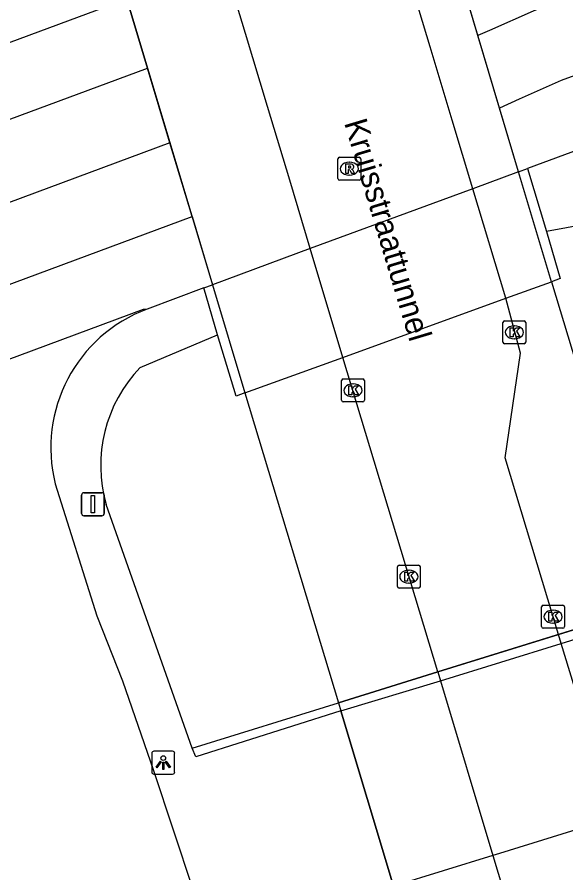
# Model space of a CAD drawing. Extents: x 160806 to 161707, y 383697 to 384148.
# Drawn here: x 161124.06 to 161148.01, y 383843.68 to 383881.02 of the extents above; entities that cross this region are included whole.
import ezdxf

# ---------------------------------------------------------------- set-up
doc = ezdxf.new("R2010")
doc.units = 0
for name, color, linetype in [('IMGEO_Berm_groen', 7, 'Continuous'), ('IMGEO_Fietspad_gesloten', 7, 'Continuous'), ('IMGEO_Groenvoorziening', 7, 'Continuous'), ('IMGEO_Kolk', 7, 'Continuous'), ('IMGEO_Lichtpunt', 7, 'Continuous'), ('IMGEO_Muur', 7, 'Continuous'), ('IMGEO_Openbare_ruimte_label', 7, 'Continuous'), ('IMGEO_OVBaan_gesloten', 7, 'Continuous'), ('IMGEO_Rijbaan_lokaal_gesloten', 7, 'Continuous'), ('IMGEO_Rioolput', 7, 'Continuous'), ('IMGEO_Tunneldeel', 7, 'Continuous'), ('IMGEO_Verkeersbordpaal', 7, 'Continuous'), ('IMGEO_Voetpad_open', 7, 'Continuous')]:
    doc.layers.add(name, color=color, linetype=linetype)

msp = doc.modelspace()

# ---------------------------------------------------------------- linework, layer by layer
at = {"layer": 'IMGEO_Berm_groen'}
msp.add_lwpolyline([(161150.814, 383872.34), (161147.163, 383871.675)], dxfattribs=at)
at = {"layer": 'IMGEO_Fietspad_gesloten'}
for points in [[(161145.381, 383868.752), (161143.943, 383873.537), (161143.043, 383876.531), (161142.082, 383879.729), (161141.127, 383882.908), (161140.189, 383886.03), (161139.898, 383886.998), (161139.762, 383887.449)], [(161138.282, 383866.176), (161136.85, 383870.932), (161135.955, 383873.904), (161134.987, 383877.121), (161134.025, 383880.315), (161133.097, 383883.398), (161132.802, 383884.376), (161132.666, 383884.829)], [(161138.282, 383866.176), (161145.381, 383868.752)], [(161138.282, 383866.176), (161145.381, 383868.752)], [(161147.686, 383854.079), (161147.449, 383854.857), (161145.358, 383861.789), (161146.034, 383866.359), (161145.381, 383868.752)], [(161142.416, 383852.446), (161138.282, 383866.176)], [(161147.686, 383854.079), (161142.416, 383852.446)], [(161153.099, 383836.327), (161150.124, 383846.082), (161147.804, 383853.693), (161147.686, 383854.079)], [(161142.416, 383852.446), (161142.534, 383852.055), (161144.827, 383844.441), (161145.8, 383841.21), (161146.837, 383837.764), (161147.656, 383835.045), (161147.77, 383834.67)]]:
    msp.add_lwpolyline(points, dxfattribs=at)
at = {"layer": 'IMGEO_Groenvoorziening'}
for points in [[(161129.436, 383865.731), (161132.81, 383867.162)], [(161131.695, 383849.124), (161127.952, 383859.751)], [(161140.482, 383843.096), (161138.194, 383850.745)]]:
    msp.add_lwpolyline(points, dxfattribs=at)
msp.add_arc((161133.83, 383861.466), 6.123, 135.8568, 196.2692, dxfattribs=at)
at = {"layer": 'IMGEO_Kolk'}
for p, q in [((161145.26, 383866.843), (161145.26, 383867.695)), ((161145.335, 383867.769), (161146.187, 383867.769)), ((161146.261, 383867.695), (161146.261, 383866.843)), ((161145.748, 383867.549), (161145.773, 383867.549)), ((161145.771, 383866.989), (161145.746, 383866.989)), ((161146.187, 383866.769), (161145.335, 383866.769)), ((161138.218, 383864.308), (161138.218, 383865.16)), ((161138.293, 383865.234), (161139.145, 383865.234)), ((161139.219, 383865.16), (161139.219, 383864.308)), ((161138.706, 383865.014), (161138.731, 383865.014)), ((161138.729, 383864.454), (161138.704, 383864.454)), ((161139.145, 383864.234), (161138.293, 383864.234)), ((161140.656, 383856.18), (161140.656, 383857.032)), ((161140.731, 383857.106), (161141.583, 383857.106)), ((161141.144, 383856.886), (161141.169, 383856.886)), ((161141.657, 383857.032), (161141.657, 383856.18)), ((161141.583, 383856.106), (161140.731, 383856.106)), ((161141.167, 383856.326), (161141.142, 383856.326)), ((161147.023, 383855.357), (161147.875, 383855.357)), ((161146.948, 383854.431), (161146.948, 383855.283)), ((161147.436, 383855.137), (161147.461, 383855.137)), ((161147.949, 383855.283), (161147.949, 383854.431)), ((161147.875, 383854.357), (161147.023, 383854.357)), ((161147.459, 383854.577), (161147.434, 383854.577))]:
    msp.add_line(p, q, dxfattribs=at)
for points in [[(161145.26, 383866.843), (161145.26, 383867.695)], [(161145.335, 383867.769), (161146.187, 383867.769)], [(161146.261, 383867.695), (161146.261, 383866.843)], [(161145.581, 383867.469), (161145.704, 383867.469), (161145.704, 383867.318), (161145.834, 383867.469), (161145.998, 383867.469), (161145.852, 383867.318), (161146.005, 383867.069), (161145.853, 383867.069), (161145.768, 383867.233), (161145.704, 383867.166), (161145.704, 383867.069), (161145.581, 383867.069), (161145.581, 383867.469)], [(161146.187, 383866.769), (161145.335, 383866.769)], [(161138.218, 383864.308), (161138.218, 383865.16)], [(161138.293, 383865.234), (161139.145, 383865.234)], [(161139.219, 383865.16), (161139.219, 383864.308)], [(161138.539, 383864.934), (161138.662, 383864.934), (161138.662, 383864.783), (161138.792, 383864.934), (161138.956, 383864.934), (161138.81, 383864.783), (161138.963, 383864.534), (161138.811, 383864.534), (161138.726, 383864.698), (161138.662, 383864.631), (161138.662, 383864.534), (161138.539, 383864.534), (161138.539, 383864.934)], [(161139.145, 383864.234), (161138.293, 383864.234)], [(161140.656, 383856.18), (161140.656, 383857.032)], [(161140.731, 383857.106), (161141.583, 383857.106)], [(161141.657, 383857.032), (161141.657, 383856.18)], [(161140.977, 383856.806), (161141.1, 383856.806), (161141.1, 383856.655), (161141.23, 383856.806), (161141.394, 383856.806), (161141.248, 383856.655), (161141.401, 383856.406), (161141.249, 383856.406), (161141.164, 383856.57), (161141.1, 383856.503), (161141.1, 383856.406), (161140.977, 383856.406), (161140.977, 383856.806)], [(161141.583, 383856.106), (161140.731, 383856.106)], [(161147.023, 383855.357), (161147.875, 383855.357)], [(161146.948, 383854.431), (161146.948, 383855.283)], [(161147.269, 383855.057), (161147.392, 383855.057), (161147.392, 383854.906), (161147.522, 383855.057), (161147.686, 383855.057), (161147.54, 383854.906), (161147.693, 383854.657), (161147.541, 383854.657), (161147.456, 383854.821), (161147.392, 383854.754), (161147.392, 383854.657), (161147.269, 383854.657), (161147.269, 383855.057)], [(161147.949, 383855.283), (161147.949, 383854.431)], [(161147.875, 383854.357), (161147.023, 383854.357)]]:
    msp.add_lwpolyline(points, dxfattribs=at)
for centre, start, end in [((161145.337, 383867.693), 91.552, 178.448), ((161145.337, 383867.693), 91.552, 178.448), ((161146.185, 383867.693), 1.552, 88.448), ((161146.185, 383867.693), 1.552, 88.448), ((161145.337, 383866.845), 181.552, 268.448), ((161145.337, 383866.845), 181.552, 268.448), ((161146.185, 383866.845), 271.552, 358.448), ((161146.185, 383866.845), 271.552, 358.448), ((161138.295, 383865.158), 91.552, 178.448), ((161138.295, 383865.158), 91.552, 178.448), ((161139.143, 383865.158), 1.552, 88.448), ((161139.143, 383865.158), 1.552, 88.448), ((161138.295, 383864.31), 181.552, 268.448), ((161138.295, 383864.31), 181.552, 268.448), ((161139.143, 383864.31), 271.552, 358.448), ((161139.143, 383864.31), 271.552, 358.448), ((161140.733, 383857.03), 91.552, 178.448), ((161140.733, 383857.03), 91.552, 178.448), ((161141.581, 383857.03), 1.552, 88.448), ((161141.581, 383857.03), 1.552, 88.448), ((161140.733, 383856.182), 181.552, 268.448), ((161140.733, 383856.182), 181.552, 268.448), ((161141.581, 383856.182), 271.552, 358.448), ((161141.581, 383856.182), 271.552, 358.448), ((161147.025, 383855.281), 91.552, 178.448), ((161147.025, 383855.281), 91.552, 178.448), ((161147.873, 383855.281), 1.552, 88.448), ((161147.873, 383855.281), 1.552, 88.448), ((161147.025, 383854.433), 181.552, 268.448), ((161147.025, 383854.433), 181.552, 268.448), ((161147.873, 383854.433), 271.552, 358.448), ((161147.873, 383854.433), 271.552, 358.448)]:
    msp.add_arc(centre, 0.0765, start, end, dxfattribs=at)
for centre, major_axis, ratio, start_param, end_param in [((161145.747, 383867.269), (-0.387, 0.002), 0.722429, 4.712389, 7.853982), ((161145.772, 383867.269), (-0.39, 0.002), 0.717154, 1.570796, 4.712389), ((161138.705, 383864.734), (-0.387, 0.002), 0.722429, 4.712389, 7.853982), ((161138.73, 383864.734), (-0.39, 0.002), 0.717154, 1.570796, 4.712389), ((161141.143, 383856.606), (-0.387, 0.002), 0.722429, 4.712389, 7.853982), ((161141.168, 383856.606), (-0.39, 0.002), 0.717154, 1.570796, 4.712389), ((161147.435, 383854.857), (-0.387, 0.002), 0.722429, 4.712389, 7.853982), ((161147.46, 383854.857), (-0.39, 0.002), 0.717154, 1.570796, 4.712389)]:
    msp.add_ellipse(centre, major_axis=major_axis, ratio=ratio, start_param=start_param, end_param=end_param, dxfattribs=at)
at = {"layer": 'IMGEO_Lichtpunt'}
for p, q in [((161129.94, 383848.891), (161129.94, 383848.084)), ((161129.94, 383848.891), (161129.94, 383848.084)), ((161130.842, 383848.986), (161130.034, 383848.986)), ((161130.842, 383848.986), (161130.034, 383848.986)), ((161130.936, 383848.084), (161130.936, 383848.891)), ((161130.936, 383848.084), (161130.936, 383848.891)), ((161130.034, 383847.99), (161130.842, 383847.99)), ((161130.034, 383847.99), (161130.842, 383847.99))]:
    msp.add_line(p, q, dxfattribs=at)
for points in [[(161130.314, 383848.555), (161130.353, 383848.527), (161130.165, 383848.265), (161130.127, 383848.292), (161130.314, 383848.555)], [(161130.416, 383848.507), (161130.463, 383848.507), (161130.463, 383848.185), (161130.416, 383848.185), (161130.416, 383848.507)], [(161130.526, 383848.527), (161130.564, 383848.554), (161130.751, 383848.292), (161130.712, 383848.264), (161130.526, 383848.527)]]:
    msp.add_lwpolyline(points, dxfattribs=at)
msp.add_circle((161130.439, 383848.689), 0.0994, dxfattribs=at)
for centre, start, end in [((161130.034, 383848.891), 90, 180), ((161130.034, 383848.891), 90, 180), ((161130.842, 383848.891), 0, 90), ((161130.842, 383848.891), 0, 90), ((161130.034, 383848.084), 180, 270), ((161130.034, 383848.084), 180, 270), ((161130.842, 383848.084), 270, 0), ((161130.842, 383848.084), 270, 360)]:
    msp.add_arc(centre, 0.0946, start, end, dxfattribs=at)
at = {"layer": 'IMGEO_Muur'}
for points in [[(161145.945, 383874.273), (161146.332, 383874.416)], [(161146.332, 383874.416), (161147.163, 383871.675)], [(161147.376, 383869.475), (161145.945, 383874.273)], [(161147.163, 383871.675), (161147.756, 383869.613), (161147.376, 383869.475)], [(161132.21, 383869.205), (161132.588, 383869.346)], [(161132.81, 383867.162), (161132.21, 383869.205)], [(161132.588, 383869.346), (161134.004, 383864.624)], [(161134.004, 383864.624), (161133.615, 383864.483), (161132.81, 383867.162)], [(161147.686, 383854.079), (161149.611, 383854.676), (161151.661, 383855.311)], [(161138.194, 383850.745), (161142.534, 383852.055), (161147.804, 383853.693), (161149.727, 383854.291), (161151.776, 383854.928)], [(161142.416, 383852.446), (161147.686, 383854.079)], [(161138.086, 383851.104), (161142.416, 383852.446)], [(161131.695, 383849.124), (161138.086, 383851.104)], [(161138.086, 383851.104), (161138.194, 383850.745)], [(161138.194, 383850.745), (161131.856, 383848.736), (161131.695, 383849.124)]]:
    msp.add_lwpolyline(points, dxfattribs=at)
at = {"layer": 'IMGEO_OVBaan_gesloten'}
msp.add_lwpolyline([(161151.764, 383846.764), (161151.824, 383846.609), (161150.124, 383846.082), (161145.114, 383844.53), (161144.827, 383844.441), (161140.482, 383843.096)], dxfattribs=at)
at = {"layer": 'IMGEO_Rijbaan_lokaal_gesloten'}
for points in [[(161214.088, 383901.528), (161187.391, 383894.279), (161172.114, 383889.9), (161162.606, 383886.956), (161151.326, 383883.114), (161148.429, 383882.073), (161146.576, 383881.284), (161144.681, 383880.444), (161144.172, 383880.216)], [(161215.028, 383898.347), (161189.294, 383891.393), (161174.166, 383886.995), (161163.764, 383883.81), (161154.369, 383880.657), (161147.808, 383878.255), (161145.964, 383877.441), (161145.116, 383877.053)], [(161144.172, 383880.216), (161143.232, 383883.37)], [(161128.848, 383881.822), (161087.876, 383866.621)], [(161129.754, 383878.799), (161128.848, 383881.822)], [(161145.116, 383877.053), (161144.172, 383880.216)], [(161070.422, 383856.806), (161129.754, 383878.799)], [(161130.73, 383875.543), (161129.754, 383878.799)], [(161145.945, 383874.273), (161145.116, 383877.053)], [(161151.735, 383876.413), (161146.332, 383874.416)], [(161130.73, 383875.543), (161100.785, 383864.404), (161068.088, 383852.305), (161054.975, 383847.445), (161009.318, 383830.547), (161001.838, 383827.792), (160966.768, 383814.836)], [(161131.695, 383872.323), (161130.73, 383875.543)], [(161145.945, 383874.273), (161143.943, 383873.537), (161136.85, 383870.932), (161132.588, 383869.346)], [(161059.41, 383845.762), (161062.999, 383847.001), (161070.515, 383849.722), (161085.394, 383855.134), (161131.695, 383872.323)], [(161131.695, 383872.323), (161132.588, 383869.346)], [(161132.21, 383869.205), (161129.731, 383868.28)], [(161129.731, 383868.28), (161129.555, 383868.265), (161106.205, 383859.577)], [(161125.724, 383860.653), (161127.533, 383854.899), (161128.653, 383852.066), (161130.01, 383848.147), (161131.736, 383842.961)]]:
    msp.add_lwpolyline(points, dxfattribs=at)
msp.add_arc((161131.996, 383862.224), 6.466, 110.5051, 194.0627, dxfattribs=at)
at = {"layer": 'IMGEO_Rioolput'}
for p, q in [((161138.058, 383873.981), (161138.058, 383874.833)), ((161138.133, 383874.907), (161138.985, 383874.907)), ((161139.059, 383874.833), (161139.059, 383873.981)), ((161138.546, 383874.687), (161138.571, 383874.687)), ((161138.569, 383874.127), (161138.544, 383874.127)), ((161138.985, 383873.907), (161138.133, 383873.907))]:
    msp.add_line(p, q, dxfattribs=at)
for points in [[(161138.058, 383873.981), (161138.058, 383874.833)], [(161138.133, 383874.907), (161138.985, 383874.907)], [(161139.059, 383874.833), (161139.059, 383873.981)], [(161138.647, 383874.605), (161138.395, 383874.607), (161138.395, 383874.207)], [(161138.573, 383874.526), (161138.519, 383874.526), (161138.519, 383874.445)], [(161138.519, 383874.445), (161138.571, 383874.445)], [(161138.395, 383874.207), (161138.519, 383874.207), (161138.519, 383874.369), (161138.53, 383874.369)], [(161138.577, 383874.34), (161138.648, 383874.207), (161138.788, 383874.207), (161138.723, 383874.333)], [(161138.985, 383873.907), (161138.133, 383873.907)]]:
    msp.add_lwpolyline(points, dxfattribs=at)
for centre, radius, start, end in [((161138.135, 383874.831), 0.0765, 91.552, 178.448), ((161138.135, 383874.831), 0.0765, 91.552, 178.448), ((161138.983, 383874.831), 0.0765, 1.552, 88.448), ((161138.983, 383874.831), 0.0765, 1.552, 88.448), ((161138.555, 383874.634), 0.19, 274.7715, 282.9687), ((161138.579, 383874.43), 0.0964, 77.0061, 93.1865), ((161138.593, 383874.487), 0.0378, 276.6634, 79.6772), ((161138.646, 383874.495), 0.109, 350.3612, 89.416), ((161138.644, 383874.495), 0.112, 277.5842, 350.9817), ((161138.529, 383874.316), 0.0533, 26.0293, 88.6989), ((161138.628, 383874.28), 0.108, 29.5134, 73.7905), ((161138.135, 383873.983), 0.0765, 181.552, 268.448), ((161138.135, 383873.983), 0.0765, 181.552, 268.448), ((161138.983, 383873.983), 0.0765, 271.552, 358.448), ((161138.983, 383873.983), 0.0765, 271.552, 358.448)]:
    msp.add_arc(centre, radius, start, end, dxfattribs=at)
for centre, major_axis, ratio, start_param, end_param in [((161138.545, 383874.407), (-0.387, 0.002), 0.722429, 4.712389, 7.853982), ((161138.57, 383874.407), (-0.39, 0.002), 0.717154, 1.570796, 4.712389)]:
    msp.add_ellipse(centre, major_axis=major_axis, ratio=ratio, start_param=start_param, end_param=end_param, dxfattribs=at)
at = {"layer": 'IMGEO_Tunneldeel'}
for points in [[(161142.214, 383886.781), (161141.926, 383887.748), (161141.791, 383888.198), (161139.762, 383887.449), (161132.666, 383884.829), (161128.417, 383883.26), (161128.299, 383883.216), (161128.402, 383882.878), (161128.519, 383882.921), (161128.553, 383882.806), (161128.848, 383881.822), (161132.588, 383869.346), (161134.004, 383864.624), (161138.282, 383866.176), (161145.381, 383868.752), (161147.376, 383869.475), (161145.945, 383874.273)], [(161154.024, 383847.47), (161153.895, 383847.899), (161153.748, 383848.385), (161153.573, 383848.966), (161151.776, 383854.928), (161151.661, 383855.311), (161149.611, 383854.676), (161142.416, 383852.446), (161138.086, 383851.104), (161138.194, 383850.745), (161140.482, 383843.096), (161142.482, 383836.411), (161143.295, 383833.692), (161143.408, 383833.314), (161147.77, 383834.67), (161154.96, 383836.906), (161157.016, 383837.543), (161156.904, 383837.916), (161156.084, 383840.634)]]:
    msp.add_lwpolyline(points, close=True, dxfattribs=at)
at = {"layer": 'IMGEO_Verkeersbordpaal'}
for p, q in [((161126.973, 383860.266), (161127.763, 383860.266)), ((161127.763, 383860.266), (161126.973, 383860.266)), ((161126.873, 383859.366), (161126.873, 383860.166)), ((161126.873, 383860.166), (161126.873, 383859.366)), ((161127.863, 383860.166), (161127.863, 383859.366)), ((161127.863, 383859.366), (161127.863, 383860.166)), ((161127.763, 383859.266), (161126.973, 383859.266)), ((161126.973, 383859.266), (161127.763, 383859.266))]:
    msp.add_line(p, q, dxfattribs=at)
msp.add_lwpolyline([(161127.293, 383860.141), (161127.443, 383860.141), (161127.443, 383859.391), (161127.293, 383859.391), (161127.293, 383860.141)], dxfattribs=at)
for centre, start, end in [((161126.973, 383860.166), 90, 180), ((161126.973, 383860.166), 90, 180), ((161127.763, 383860.166), 0, 90), ((161127.763, 383860.166), 360, 90), ((161126.973, 383859.366), 180, 270), ((161126.973, 383859.366), 180, 270), ((161127.763, 383859.366), 270, 0), ((161127.763, 383859.366), 270, 0)]:
    msp.add_arc(centre, 0.1, start, end, dxfattribs=at)
at = {"layer": 'IMGEO_Voetpad_open'}
for points in [[(161145.381, 383868.752), (161147.376, 383869.475), (161145.945, 383874.273), (161142.214, 383886.781), (161141.926, 383887.748), (161141.791, 383888.198), (161139.762, 383887.449)], [(161132.666, 383884.829), (161128.417, 383883.26), (161128.299, 383883.216), (161128.402, 383882.878), (161128.519, 383882.921), (161128.553, 383882.806), (161128.848, 383881.822), (161132.588, 383869.346), (161134.004, 383864.624), (161138.282, 383866.176)], [(161145.381, 383868.752), (161147.376, 383869.475)], [(161147.376, 383869.475), (161149.378, 383862.885)], [(161134.004, 383864.624), (161138.282, 383866.176)], [(161134.004, 383864.624), (161138.086, 383851.104)], [(161153.099, 383836.327), (161154.96, 383836.906), (161157.016, 383837.543), (161156.904, 383837.916), (161156.084, 383840.634), (161154.024, 383847.47), (161153.895, 383847.899), (161153.748, 383848.385), (161153.573, 383848.966), (161151.776, 383854.928), (161151.661, 383855.311), (161149.611, 383854.676), (161147.686, 383854.079)], [(161142.416, 383852.446), (161138.086, 383851.104), (161138.194, 383850.745), (161140.482, 383843.096), (161142.482, 383836.411), (161143.295, 383833.692), (161143.408, 383833.314), (161147.77, 383834.67)]]:
    msp.add_lwpolyline(points, dxfattribs=at)

# ---------------------------------------------------------------- texts
at = {"layer": 'IMGEO_Openbare_ruimte_label'}
msp.add_text('Kruisstraattunnel', height=1, rotation=286.6773, dxfattribs=at).set_placement((161138.325, 383876.415))

doc.saveas('drawing.dxf')
